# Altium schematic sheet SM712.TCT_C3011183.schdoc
size 127 x 101 mm
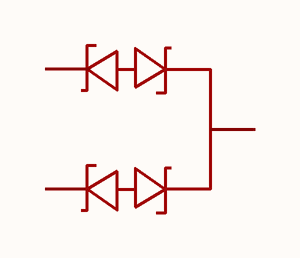
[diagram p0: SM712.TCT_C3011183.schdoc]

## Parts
U?  sm712.tct_c3011183  [SOT-23-3_L2.9-W1.3-P0.95-LS2.4-BR]  (value not drawn)

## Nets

Not connected (* = marked no-connect by the designer): U? 1 2 3

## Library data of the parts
U? = sm712.tct_c3011183: 反向截止电压(Vrwm):7V;钳位电压:12V;峰值脉冲电流(Ipp):17A@8/20us;峰值脉冲功率(Ppp):400W@8/20us;击穿电压:7.5V;; Manufacturer: TECH PUBLIC(台舟); AddInBom: yes; ModelId: c62791f0466c4ae2a892c056b845b0ca; ModelName: SOT-23-3P_L2.9-W1.3-H1.0-LS2.4-P0.95; ModelTransform: 98.425,114.173,0,180,0,0,0.0005,-0.0005,0; Reverse Stand-Off Voltage (Vrwm): 7V; Clamping Voltage: 12V; Voltage - Breakdown: 7.5V; Reverse Leakage Current (Ir): 2uA; level of protection: IEC 61000-4-4；IEC 61000-4-5；IEC 61000-4-2; Junction Capacitance: 75pF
